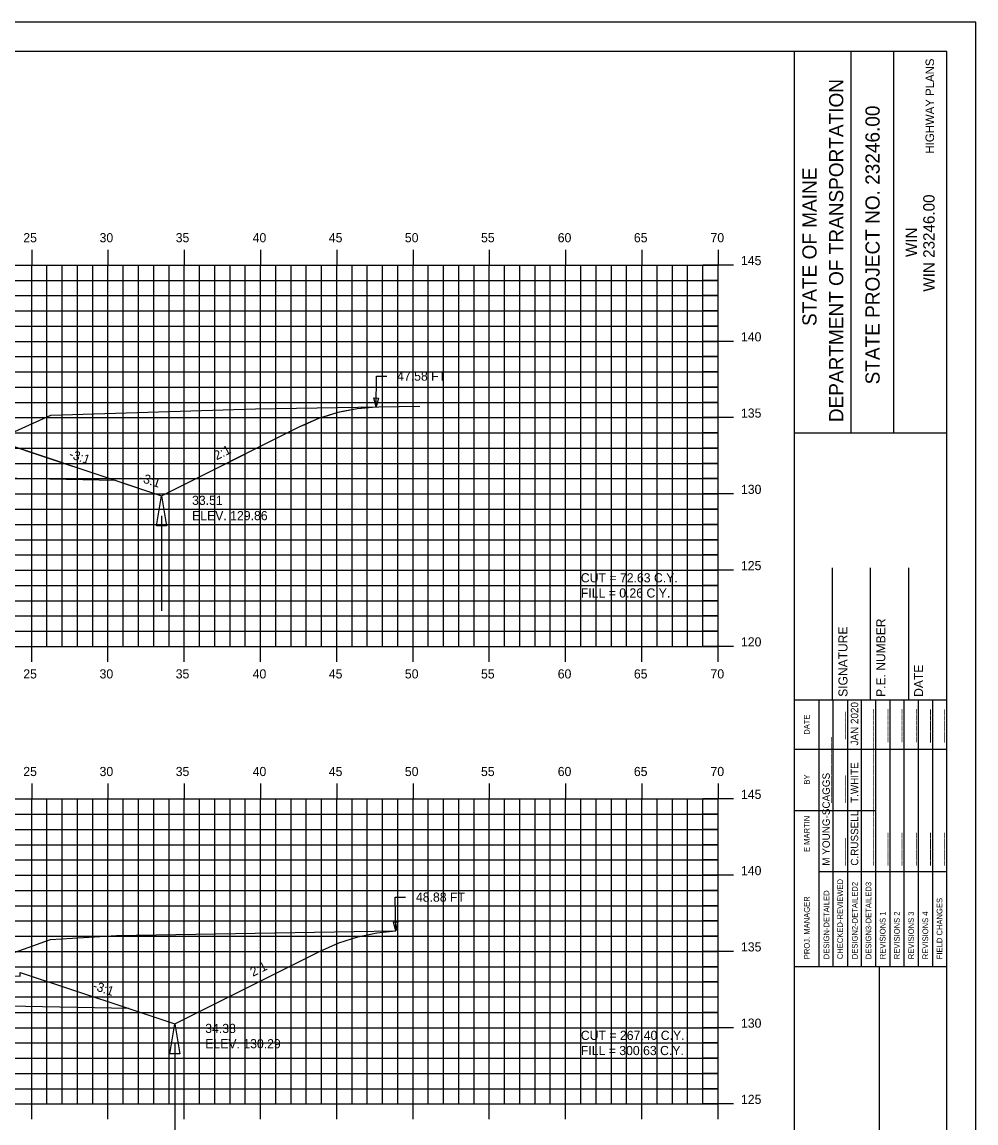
# Model space of a CAD drawing. Extents: x 1145416 to 1145586, y 608981 to 609091.
# Drawn here: x 1145523.3 to 1145585.8, y 609019.1 to 609091.3 of the extents above; entities that cross this region are included whole.
import ezdxf

# ---------------------------------------------------------------- set-up
doc = ezdxf.new("R2010")
doc.units = 0
for name, color, linetype in [('ANNOTATION', 7, 'Continuous'), ('BORDER', 7, 'Continuous'), ('D_Drainage_Ditch_Line', 7, 'Continuous'), ('D_Roadway_SlopeLines', 7, 'Continuous'), ('D_Roadway_SubGrade', 7, 'Continuous'), ('D_Text_Standard', 7, 'Continuous'), ('H_V ANNOTATION', 7, 'Continuous'), ('HIGHWAY_TITLE', 7, 'Continuous'), ('MAJOR', 7, 'Continuous'), ('MINOR', 7, 'Continuous'), ('PLOT BOUNDARY', 7, 'Continuous'), ('S_Roadway_Centerline', 7, 'Continuous')]:
    doc.layers.add(name, color=color, linetype=linetype)

msp = doc.modelspace()

# ---------------------------------------------------------------- linework, layer by layer
msp.add_lwpolyline([(1145522.208, 609063.612), (1145523.869, 609063.058), (1145529.401, 609061.214), (1145530.093, 609060.983), (1145532.401, 609060.214), (1145534.491, 609061.259), (1145541.469, 609064.748), (1145541.758, 609064.875), (1145542.719, 609065.298), (1145543.008, 609065.39), (1145543.969, 609065.696), (1145544.258, 609065.753), (1145545.219, 609065.944), (1145545.508, 609065.966), (1145546.469, 609066.04)])
at = {"layer": 'BORDER'}
for p, q in [((1145573.889, 608984.335), (1145573.889, 609089.335)), ((1145577.617, 609064.332), (1145577.617, 609089.332)), ((1145580.412, 609064.332), (1145580.412, 609089.332)), ((1145573.89, 609064.329), (1145583.889, 609064.329)), ((1145576.389, 609046.838), (1145576.389, 609055.485)), ((1145578.889, 609046.838), (1145578.889, 609055.485)), ((1145581.389, 609046.838), (1145581.389, 609055.485)), ((1145573.889, 609046.838), (1145583.889, 609046.838)), ((1145573.889, 609029.338), (1145583.889, 609029.338)), ((1145579.48, 608994.338), (1145579.48, 609029.338))]:
    msp.add_line(p, q, dxfattribs=at)
msp.add_lwpolyline([(1145423.889, 608984.335), (1145583.889, 608984.335), (1145583.889, 609089.335), (1145423.889, 609089.335)], close=True, dxfattribs=at)
for points in [[(1145575.504, 609043.588), (1145575.504, 609046.838)], [(1145576.436, 609029.341), (1145576.436, 609046.838)], [(1145577.368, 609046.838), (1145577.368, 609029.341)], [(1145578.3, 609029.341), (1145578.3, 609046.838)], [(1145579.231, 609029.341), (1145579.231, 609046.838)], [(1145580.163, 609029.341), (1145580.163, 609046.838)], [(1145581.095, 609029.341), (1145581.095, 609046.838)], [(1145582.026, 609029.341), (1145582.026, 609046.838)], [(1145582.958, 609029.341), (1145582.958, 609046.838)], [(1145575.505, 609029.341), (1145575.505, 609046.132)], [(1145573.889, 609043.588), (1145583.889, 609043.588)], [(1145573.889, 609039.588), (1145575.505, 609039.588)], [(1145575.504, 609039.588), (1145579.23, 609039.588)], [(1145575.504, 609035.588), (1145583.889, 609035.588)]]:
    msp.add_lwpolyline(points, dxfattribs=at)
at = {"layer": 'D_Drainage_Ditch_Line'}
for p, q in [((1145532.401, 609058.902), (1145532.401, 609052.658)), ((1145533.264, 609024.275), (1145533.263, 609018.032))]:
    msp.add_line(p, q, dxfattribs=at)
for points in [[(1145532.729, 609058.246), (1145532.073, 609058.246), (1145532.401, 609060.214)], [(1145533.592, 609023.619), (1145532.936, 609023.619), (1145533.264, 609025.588)]]:
    msp.add_lwpolyline(points, close=True, dxfattribs=at)
at = {"layer": 'D_Roadway_SlopeLines'}
for points in [[(1145532.401, 609060.214), (1145541.469, 609064.748), (1145542.719, 609065.298), (1145543.969, 609065.696), (1145545.219, 609065.944), (1145546.469, 609066.04)], [(1145529.401, 609061.214), (1145532.401, 609060.214)], [(1145533.264, 609025.588), (1145542.766, 609030.339), (1145544.016, 609030.892), (1145545.266, 609031.3), (1145546.516, 609031.564), (1145547.766, 609031.683)], [(1145530.264, 609026.588), (1145533.264, 609025.588)]]:
    msp.add_lwpolyline(points, dxfattribs=at)
at = {"layer": 'D_Roadway_SubGrade'}
for points in [[(1145509.889, 609063.688), (1145509.889, 609063.854), (1145522.208, 609063.362), (1145522.208, 609063.612), (1145522.209, 609063.612), (1145529.401, 609061.214), (1145509.889, 609061.604)], [(1145509.889, 609029.079), (1145509.889, 609029.245), (1145523.13, 609028.716), (1145523.13, 609028.966), (1145523.13, 609028.966), (1145530.264, 609026.588), (1145509.889, 609026.995)]]:
    msp.add_lwpolyline(points, close=True, dxfattribs=at)
at = {"layer": 'D_Text_Standard'}
for points in [[(1145546.469, 609066.04), (1145546.485, 609068.059), (1145547.165, 609068.059)], [(1145547.766, 609031.683), (1145547.719, 609033.898), (1145548.399, 609033.898)]]:
    msp.add_lwpolyline(points, dxfattribs=at)
for points in [[(1145546.469, 609066.04), (1145546.328, 609066.624), (1145546.619, 609066.621)], [(1145547.766, 609031.683), (1145547.608, 609032.262), (1145547.899, 609032.268)]]:
    msp.add_lwpolyline(points, close=True, dxfattribs=at)
at = {"layer": 'MAJOR'}
for p, q in [((1145523.889, 609076.337), (1145523.889, 609075.335)), ((1145528.889, 609076.337), (1145528.889, 609075.335)), ((1145533.889, 609076.337), (1145533.889, 609075.335)), ((1145538.889, 609076.337), (1145538.889, 609075.335)), ((1145543.889, 609076.337), (1145543.889, 609075.335)), ((1145548.889, 609076.337), (1145548.889, 609075.335)), ((1145553.889, 609076.337), (1145553.889, 609075.335)), ((1145558.889, 609076.337), (1145558.889, 609075.335)), ((1145563.889, 609076.337), (1145563.889, 609075.335)), ((1145568.889, 609076.337), (1145568.889, 609075.335)), ((1145428.889, 609075.335), (1145568.889, 609075.335)), ((1145428.889, 609075.335), (1145568.889, 609075.335)), ((1145523.889, 609050.335), (1145523.889, 609075.335)), ((1145528.889, 609050.335), (1145528.889, 609075.335)), ((1145533.889, 609050.335), (1145533.889, 609075.335)), ((1145538.889, 609050.335), (1145538.889, 609075.335)), ((1145543.889, 609050.335), (1145543.889, 609075.335)), ((1145548.889, 609050.335), (1145548.889, 609075.335)), ((1145553.889, 609050.335), (1145553.889, 609075.335)), ((1145558.889, 609050.335), (1145558.889, 609075.335)), ((1145563.889, 609050.335), (1145563.889, 609075.335)), ((1145569.891, 609075.335), (1145567.887, 609075.335)), ((1145568.889, 609050.335), (1145568.889, 609075.335)), ((1145568.889, 609050.335), (1145568.889, 609075.335)), ((1145428.889, 609070.335), (1145568.889, 609070.335)), ((1145569.891, 609070.335), (1145567.887, 609070.335)), ((1145428.889, 609065.335), (1145568.889, 609065.335)), ((1145569.891, 609065.335), (1145567.887, 609065.335)), ((1145428.889, 609060.335), (1145568.889, 609060.335)), ((1145569.891, 609060.335), (1145567.887, 609060.335)), ((1145428.889, 609055.335), (1145568.889, 609055.335)), ((1145569.891, 609055.335), (1145567.887, 609055.335)), ((1145428.889, 609050.335), (1145568.889, 609050.335)), ((1145428.889, 609050.335), (1145568.889, 609050.335)), ((1145523.889, 609049.333), (1145523.889, 609050.335)), ((1145528.889, 609049.333), (1145528.889, 609050.335)), ((1145533.889, 609049.333), (1145533.889, 609050.335)), ((1145538.889, 609049.333), (1145538.889, 609050.335)), ((1145543.889, 609049.333), (1145543.889, 609050.335)), ((1145548.889, 609049.333), (1145548.889, 609050.335)), ((1145553.889, 609049.333), (1145553.889, 609050.335)), ((1145558.889, 609049.333), (1145558.889, 609050.335)), ((1145563.889, 609049.333), (1145563.889, 609050.335)), ((1145569.891, 609050.335), (1145567.887, 609050.335)), ((1145568.889, 609049.333), (1145568.889, 609050.335)), ((1145523.889, 609041.337), (1145523.889, 609040.335)), ((1145528.889, 609041.337), (1145528.889, 609040.335)), ((1145533.889, 609041.337), (1145533.889, 609040.335)), ((1145538.889, 609041.337), (1145538.889, 609040.335)), ((1145543.889, 609041.337), (1145543.889, 609040.335)), ((1145548.889, 609041.337), (1145548.889, 609040.335)), ((1145553.889, 609041.337), (1145553.889, 609040.335)), ((1145558.889, 609041.337), (1145558.889, 609040.335)), ((1145563.889, 609041.337), (1145563.889, 609040.335)), ((1145568.889, 609041.337), (1145568.889, 609040.335)), ((1145428.889, 609040.335), (1145568.889, 609040.335)), ((1145428.889, 609040.335), (1145568.889, 609040.335)), ((1145523.889, 609020.335), (1145523.889, 609040.335)), ((1145528.889, 609020.335), (1145528.889, 609040.335)), ((1145533.889, 609020.335), (1145533.889, 609040.335)), ((1145538.889, 609020.335), (1145538.889, 609040.335)), ((1145543.889, 609020.335), (1145543.889, 609040.335)), ((1145548.889, 609020.335), (1145548.889, 609040.335)), ((1145553.889, 609020.335), (1145553.889, 609040.335)), ((1145558.889, 609020.335), (1145558.889, 609040.335)), ((1145563.889, 609020.335), (1145563.889, 609040.335)), ((1145569.891, 609040.335), (1145567.887, 609040.335)), ((1145568.889, 609020.335), (1145568.889, 609040.335)), ((1145568.889, 609020.335), (1145568.889, 609040.335)), ((1145428.889, 609035.335), (1145568.889, 609035.335)), ((1145569.891, 609035.335), (1145567.887, 609035.335)), ((1145428.889, 609030.335), (1145568.889, 609030.335)), ((1145569.891, 609030.335), (1145567.887, 609030.335)), ((1145428.889, 609025.335), (1145568.889, 609025.335)), ((1145569.891, 609025.335), (1145567.887, 609025.335)), ((1145428.889, 609020.335), (1145568.889, 609020.335)), ((1145428.889, 609020.335), (1145568.889, 609020.335)), ((1145523.889, 609019.333), (1145523.889, 609020.335)), ((1145528.889, 609019.333), (1145528.889, 609020.335)), ((1145533.889, 609019.333), (1145533.889, 609020.335)), ((1145538.889, 609019.333), (1145538.889, 609020.335)), ((1145543.889, 609019.333), (1145543.889, 609020.335)), ((1145548.889, 609019.333), (1145548.889, 609020.335)), ((1145553.889, 609019.333), (1145553.889, 609020.335)), ((1145558.889, 609019.333), (1145558.889, 609020.335)), ((1145563.889, 609019.333), (1145563.889, 609020.335)), ((1145569.891, 609020.335), (1145567.887, 609020.335)), ((1145568.889, 609019.333), (1145568.889, 609020.335))]:
    msp.add_line(p, q, dxfattribs=at)
at = {"layer": 'MINOR'}
for p, q in [((1145524.889, 609050.335), (1145524.889, 609075.335)), ((1145525.889, 609050.335), (1145525.889, 609075.335)), ((1145526.889, 609050.335), (1145526.889, 609075.335)), ((1145527.889, 609050.335), (1145527.889, 609075.335)), ((1145529.889, 609050.335), (1145529.889, 609075.335)), ((1145530.889, 609050.335), (1145530.889, 609075.335)), ((1145531.889, 609050.335), (1145531.889, 609075.335)), ((1145532.889, 609050.335), (1145532.889, 609075.335)), ((1145534.889, 609050.335), (1145534.889, 609075.335)), ((1145535.889, 609050.335), (1145535.889, 609075.335)), ((1145536.889, 609050.335), (1145536.889, 609075.335)), ((1145537.889, 609050.335), (1145537.889, 609075.335)), ((1145539.889, 609050.335), (1145539.889, 609075.335)), ((1145540.889, 609050.335), (1145540.889, 609075.335)), ((1145541.889, 609050.335), (1145541.889, 609075.335)), ((1145542.889, 609050.335), (1145542.889, 609075.335)), ((1145544.889, 609050.335), (1145544.889, 609075.335)), ((1145545.889, 609050.335), (1145545.889, 609075.335)), ((1145546.889, 609050.335), (1145546.889, 609075.335)), ((1145547.889, 609050.335), (1145547.889, 609075.335)), ((1145549.889, 609050.335), (1145549.889, 609075.335)), ((1145550.889, 609050.335), (1145550.889, 609075.335)), ((1145551.889, 609050.335), (1145551.889, 609075.335)), ((1145552.889, 609050.335), (1145552.889, 609075.335)), ((1145554.889, 609050.335), (1145554.889, 609075.335)), ((1145555.889, 609050.335), (1145555.889, 609075.335)), ((1145556.889, 609050.335), (1145556.889, 609075.335)), ((1145557.889, 609050.335), (1145557.889, 609075.335)), ((1145559.889, 609050.335), (1145559.889, 609075.335)), ((1145560.889, 609050.335), (1145560.889, 609075.335)), ((1145561.889, 609050.335), (1145561.889, 609075.335)), ((1145562.889, 609050.335), (1145562.889, 609075.335)), ((1145564.889, 609050.335), (1145564.889, 609075.335)), ((1145565.889, 609050.335), (1145565.889, 609075.335)), ((1145566.889, 609050.335), (1145566.889, 609075.335)), ((1145567.889, 609050.335), (1145567.889, 609075.335)), ((1145428.889, 609074.335), (1145568.889, 609074.335)), ((1145568.889, 609074.335), (1145567.887, 609074.335)), ((1145428.889, 609073.335), (1145568.889, 609073.335)), ((1145568.889, 609073.335), (1145567.887, 609073.335)), ((1145428.889, 609072.335), (1145568.889, 609072.335)), ((1145568.889, 609072.335), (1145567.887, 609072.335)), ((1145428.889, 609071.335), (1145568.889, 609071.335)), ((1145568.889, 609071.335), (1145567.887, 609071.335)), ((1145428.889, 609069.335), (1145568.889, 609069.335)), ((1145568.889, 609069.335), (1145567.887, 609069.335)), ((1145428.889, 609068.335), (1145568.889, 609068.335)), ((1145568.889, 609068.335), (1145567.887, 609068.335)), ((1145428.889, 609067.335), (1145568.889, 609067.335)), ((1145568.889, 609067.335), (1145567.887, 609067.335)), ((1145428.889, 609066.335), (1145568.889, 609066.335)), ((1145568.889, 609066.335), (1145567.887, 609066.335)), ((1145428.889, 609064.335), (1145568.889, 609064.335)), ((1145568.889, 609064.335), (1145567.887, 609064.335)), ((1145428.889, 609063.335), (1145568.889, 609063.335)), ((1145568.889, 609063.335), (1145567.887, 609063.335)), ((1145428.889, 609062.335), (1145568.889, 609062.335)), ((1145568.889, 609062.335), (1145567.887, 609062.335)), ((1145428.889, 609061.335), (1145568.889, 609061.335)), ((1145568.889, 609061.335), (1145567.887, 609061.335)), ((1145428.889, 609059.335), (1145568.889, 609059.335)), ((1145568.889, 609059.335), (1145567.887, 609059.335)), ((1145428.889, 609058.335), (1145568.889, 609058.335)), ((1145568.889, 609058.335), (1145567.887, 609058.335)), ((1145428.889, 609057.335), (1145568.889, 609057.335)), ((1145568.889, 609057.335), (1145567.887, 609057.335)), ((1145428.889, 609056.335), (1145568.889, 609056.335)), ((1145568.889, 609056.335), (1145567.887, 609056.335)), ((1145428.889, 609054.335), (1145568.889, 609054.335)), ((1145568.889, 609054.335), (1145567.887, 609054.335)), ((1145428.889, 609053.335), (1145568.889, 609053.335)), ((1145568.889, 609053.335), (1145567.887, 609053.335)), ((1145428.889, 609052.335), (1145568.889, 609052.335)), ((1145568.889, 609052.335), (1145567.887, 609052.335)), ((1145428.889, 609051.335), (1145568.889, 609051.335)), ((1145568.889, 609051.335), (1145567.887, 609051.335)), ((1145524.889, 609020.335), (1145524.889, 609040.335)), ((1145525.889, 609020.335), (1145525.889, 609040.335)), ((1145526.889, 609020.335), (1145526.889, 609040.335)), ((1145527.889, 609020.335), (1145527.889, 609040.335)), ((1145529.889, 609020.335), (1145529.889, 609040.335)), ((1145530.889, 609020.335), (1145530.889, 609040.335)), ((1145531.889, 609020.335), (1145531.889, 609040.335)), ((1145532.889, 609020.335), (1145532.889, 609040.335)), ((1145534.889, 609020.335), (1145534.889, 609040.335)), ((1145535.889, 609020.335), (1145535.889, 609040.335)), ((1145536.889, 609020.335), (1145536.889, 609040.335)), ((1145537.889, 609020.335), (1145537.889, 609040.335)), ((1145539.889, 609020.335), (1145539.889, 609040.335)), ((1145540.889, 609020.335), (1145540.889, 609040.335)), ((1145541.889, 609020.335), (1145541.889, 609040.335)), ((1145542.889, 609020.335), (1145542.889, 609040.335)), ((1145544.889, 609020.335), (1145544.889, 609040.335)), ((1145545.889, 609020.335), (1145545.889, 609040.335)), ((1145546.889, 609020.335), (1145546.889, 609040.335)), ((1145547.889, 609020.335), (1145547.889, 609040.335)), ((1145549.889, 609020.335), (1145549.889, 609040.335)), ((1145550.889, 609020.335), (1145550.889, 609040.335)), ((1145551.889, 609020.335), (1145551.889, 609040.335)), ((1145552.889, 609020.335), (1145552.889, 609040.335)), ((1145554.889, 609020.335), (1145554.889, 609040.335)), ((1145555.889, 609020.335), (1145555.889, 609040.335)), ((1145556.889, 609020.335), (1145556.889, 609040.335)), ((1145557.889, 609020.335), (1145557.889, 609040.335)), ((1145559.889, 609020.335), (1145559.889, 609040.335)), ((1145560.889, 609020.335), (1145560.889, 609040.335)), ((1145561.889, 609020.335), (1145561.889, 609040.335)), ((1145562.889, 609020.335), (1145562.889, 609040.335)), ((1145564.889, 609020.335), (1145564.889, 609040.335)), ((1145565.889, 609020.335), (1145565.889, 609040.335)), ((1145566.889, 609020.335), (1145566.889, 609040.335)), ((1145567.889, 609020.335), (1145567.889, 609040.335)), ((1145428.889, 609039.335), (1145568.889, 609039.335)), ((1145568.889, 609039.335), (1145567.887, 609039.335)), ((1145428.889, 609038.335), (1145568.889, 609038.335)), ((1145568.889, 609038.335), (1145567.887, 609038.335)), ((1145428.889, 609037.335), (1145568.889, 609037.335)), ((1145568.889, 609037.335), (1145567.887, 609037.335)), ((1145428.889, 609036.335), (1145568.889, 609036.335)), ((1145568.889, 609036.335), (1145567.887, 609036.335)), ((1145428.889, 609034.335), (1145568.889, 609034.335)), ((1145568.889, 609034.335), (1145567.887, 609034.335)), ((1145428.889, 609033.335), (1145568.889, 609033.335)), ((1145568.889, 609033.335), (1145567.887, 609033.335)), ((1145428.889, 609032.335), (1145568.889, 609032.335)), ((1145568.889, 609032.335), (1145567.887, 609032.335)), ((1145428.889, 609031.335), (1145568.889, 609031.335)), ((1145568.889, 609031.335), (1145567.887, 609031.335)), ((1145428.889, 609029.335), (1145568.889, 609029.335)), ((1145568.889, 609029.335), (1145567.887, 609029.335)), ((1145428.889, 609028.335), (1145568.889, 609028.335)), ((1145568.889, 609028.335), (1145567.887, 609028.335)), ((1145568.889, 609027.335), (1145428.889, 609027.335)), ((1145568.889, 609027.335), (1145567.887, 609027.335)), ((1145428.889, 609026.335), (1145568.889, 609026.335)), ((1145568.889, 609026.335), (1145567.887, 609026.335)), ((1145428.889, 609024.335), (1145568.889, 609024.335)), ((1145568.889, 609024.335), (1145567.887, 609024.335)), ((1145428.889, 609023.335), (1145568.889, 609023.335)), ((1145568.889, 609023.335), (1145567.887, 609023.335)), ((1145428.889, 609022.335), (1145568.889, 609022.335)), ((1145568.889, 609022.335), (1145567.887, 609022.335)), ((1145428.889, 609021.335), (1145568.889, 609021.335)), ((1145568.889, 609021.335), (1145567.887, 609021.335))]:
    msp.add_line(p, q, dxfattribs=at)
at = {"layer": 'PLOT BOUNDARY'}
msp.add_lwpolyline([(1145415.795, 608981.276), (1145585.795, 608981.276), (1145585.795, 609091.276), (1145415.795, 609091.276)], close=True, dxfattribs=at)
at = {"layer": 'S_Roadway_Centerline'}
for points in [[(1145430.769, 609061.931), (1145442.218, 609062.06), (1145448.126, 609062.101), (1145457.595, 609062.232), (1145466.917, 609062.286), (1145471.752, 609062.283), (1145476.11, 609062.196), (1145480.459, 609062.265), (1145483.944, 609062.24), (1145485.607, 609062.408), (1145492.15, 609062.548), (1145496.357, 609062.594), (1145500.535, 609062.539), (1145507.817, 609062.387), (1145509.188, 609062.268), (1145511.771, 609062.039), (1145512.918, 609061.708), (1145514.583, 609060.924), (1145521.608, 609063.91), (1145525.146, 609065.496), (1145538.554, 609065.907), (1145549.34, 609066.089)], [(1145518.014, 609028.583), (1145525.127, 609031.11), (1145529.449, 609031.371), (1145547.626, 609031.678)]]:
    msp.add_lwpolyline(points, dxfattribs=at)

# ---------------------------------------------------------------- texts
at = {"layer": 'ANNOTATION'}
for s, rotation, p in [('-3:1', 341.56529, (1145526.284, 609062.707)), ('2:1', 26.56505, (1145536.008, 609062.535)), ('-3:1', 341.56505, (1145530.897, 609061.17)), ('2:1', 26.56505, (1145538.389, 609028.668)), ('-3:1', 341.56522, (1145527.846, 609027.848))]:
    msp.add_text(s, height=0.6, rotation=rotation, dxfattribs=at).set_placement(p)
at = {"layer": 'BORDER'}
for s, height, p in [('DEPARTMENT OF TRANSPORTATION', 0.93176, (1145577.096, 609065.041)), ('STATE PROJECT NO. 23246.00', 0.93176, (1145579.481, 609067.517)), ('STATE OF MAINE', 0.93176, (1145575.344, 609071.347)), ('WIN 23246.00', 0.74527, (1145583.084, 609073.596)), ('WIN', 0.7453, (1145581.925, 609075.865)), ('SIGNATURE', 0.5906, (1145577.369, 609047.03)), ('P.E. NUMBER', 0.59055, (1145579.849, 609047.03)), ('DATE', 0.5906, (1145582.33, 609047.03)), ('JAN 2020', 0.4845, (1145578.075, 609043.843)), ('DATE', 0.3714, (1145574.893, 609044.544)), ('_____', 0.4845, (1145577.106, 609044.243)), ('______', 0.4845, (1145578.969, 609044.063)), ('______', 0.4845, (1145579.901, 609044.065)), ('______', 0.4845, (1145580.833, 609044.067)), ('______', 0.4845, (1145581.764, 609044.067)), ('______', 0.4845, (1145582.696, 609044.036)), ('______', 0.4845, (1145583.628, 609044.036)), ('____________', 0.48455, (1145576.212, 609040.073)), ('____________', 0.48455, (1145578.969, 609040.073)), ('T.WHITE', 0.4845, (1145578.075, 609040.073)), ('BY', 0.3714, (1145574.893, 609041.273)), ('M YOUNG-SCAGGS', 0.48455, (1145576.212, 609035.961)), ('_____', 0.4845, (1145577.143, 609040.073)), ('____________', 0.48455, (1145578.969, 609035.961)), ('C.RUSSELL', 0.4845, (1145578.075, 609035.961)), ('E MARTIN', 0.3727, (1145574.893, 609036.855)), ('_____', 0.4845, (1145577.106, 609035.961)), ('______', 0.4845, (1145579.901, 609035.961)), ('______', 0.4845, (1145580.833, 609035.961)), ('______', 0.4845, (1145581.764, 609035.961)), ('______', 0.4845, (1145582.696, 609035.961)), ('______', 0.4845, (1145583.628, 609035.961)), ('CHECKED-REVIEWED', 0.37275, (1145577.07, 609029.826)), ('DESIGN2-DETAILED2', 0.37275, (1145578.039, 609029.826)), ('DESIGN3-DETAILED3', 0.37275, (1145578.933, 609029.826)), ('DESIGN-DETAILED', 0.37275, (1145576.175, 609029.826)), ('PROJ. MANAGER', 0.37275, (1145574.893, 609029.826)), ('FIELD CHANGES', 0.37275, (1145583.592, 609029.826)), ('REVISIONS 1', 0.37275, (1145579.865, 609029.826)), ('REVISIONS 2', 0.37275, (1145580.796, 609029.826)), ('REVISIONS 3', 0.37275, (1145581.728, 609029.826)), ('REVISIONS 4', 0.37275, (1145582.66, 609029.826))]:
    msp.add_text(s, height=height, rotation=90, dxfattribs=at).set_placement(p)
at = {"layer": 'D_Text_Standard'}
for s, p in [('47.58 FT', (1145547.845, 609067.759)), ('33.51', (1145534.401, 609059.614)), ('ELEV. 129.86', (1145534.401, 609058.612)), ('CUT = 72.63 C.Y.', (1145559.889, 609054.535)), ('FILL = 0.26 C.Y.', (1145559.889, 609053.539)), ('48.88 FT', (1145549.079, 609033.598)), ('34.38', (1145535.264, 609024.988)), ('CUT = 267.40 C.Y.', (1145559.889, 609024.535)), ('ELEV. 130.29', (1145535.264, 609023.986)), ('FILL = 300.63 C.Y.', (1145559.889, 609023.539))]:
    msp.add_text(s, height=0.6, dxfattribs=at).set_placement(p)
at = {"layer": 'H_V ANNOTATION'}
for s, p in [('25', (1145523.335, 609076.835)), ('30', (1145528.337, 609076.835)), ('35', (1145533.329, 609076.835)), ('40', (1145538.375, 609076.835)), ('45', (1145543.367, 609076.835)), ('50', (1145548.353, 609076.835)), ('55', (1145553.345, 609076.835)), ('60', (1145558.375, 609076.835)), ('65', (1145563.367, 609076.835)), ('70', (1145568.391, 609076.835)), ('145', (1145570.389, 609075.335)), ('140', (1145570.389, 609070.335)), ('135', (1145570.389, 609065.335)), ('130', (1145570.389, 609060.335)), ('125', (1145570.389, 609055.335)), ('120', (1145570.389, 609050.335)), ('25', (1145523.335, 609048.235)), ('30', (1145528.337, 609048.235)), ('35', (1145533.329, 609048.235)), ('40', (1145538.375, 609048.235)), ('45', (1145543.367, 609048.235)), ('50', (1145548.353, 609048.235)), ('55', (1145553.345, 609048.235)), ('60', (1145558.375, 609048.235)), ('65', (1145563.367, 609048.235)), ('70', (1145568.391, 609048.235)), ('25', (1145523.335, 609041.835)), ('30', (1145528.337, 609041.835)), ('35', (1145533.329, 609041.835)), ('40', (1145538.375, 609041.835)), ('45', (1145543.367, 609041.835)), ('50', (1145548.353, 609041.835)), ('55', (1145553.345, 609041.835)), ('60', (1145558.375, 609041.835)), ('65', (1145563.367, 609041.835)), ('70', (1145568.391, 609041.835)), ('145', (1145570.389, 609040.335)), ('140', (1145570.389, 609035.335)), ('135', (1145570.389, 609030.335)), ('130', (1145570.389, 609025.335)), ('125', (1145570.389, 609020.335))]:
    msp.add_text(s, height=0.6, dxfattribs=at).set_placement(p)
at = {"layer": 'HIGHWAY_TITLE'}
msp.add_text('HIGHWAY PLANS', height=0.55901, rotation=90, dxfattribs=at).set_placement((1145583.047, 609082.65))

doc.saveas('drawing.dxf')
